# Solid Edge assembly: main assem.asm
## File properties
Author: Deepak Maini
Template: Normal.asm
Last saved by: MYPC
Revision: 12
Application: Solid Edge
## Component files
master rod.par
piston.par
piston pin.par
arti subassm.asm
piston pin plug.par
piston ring.par
master rod bearing.par
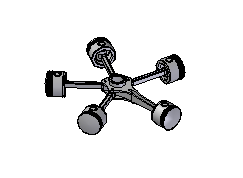
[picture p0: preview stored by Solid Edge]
